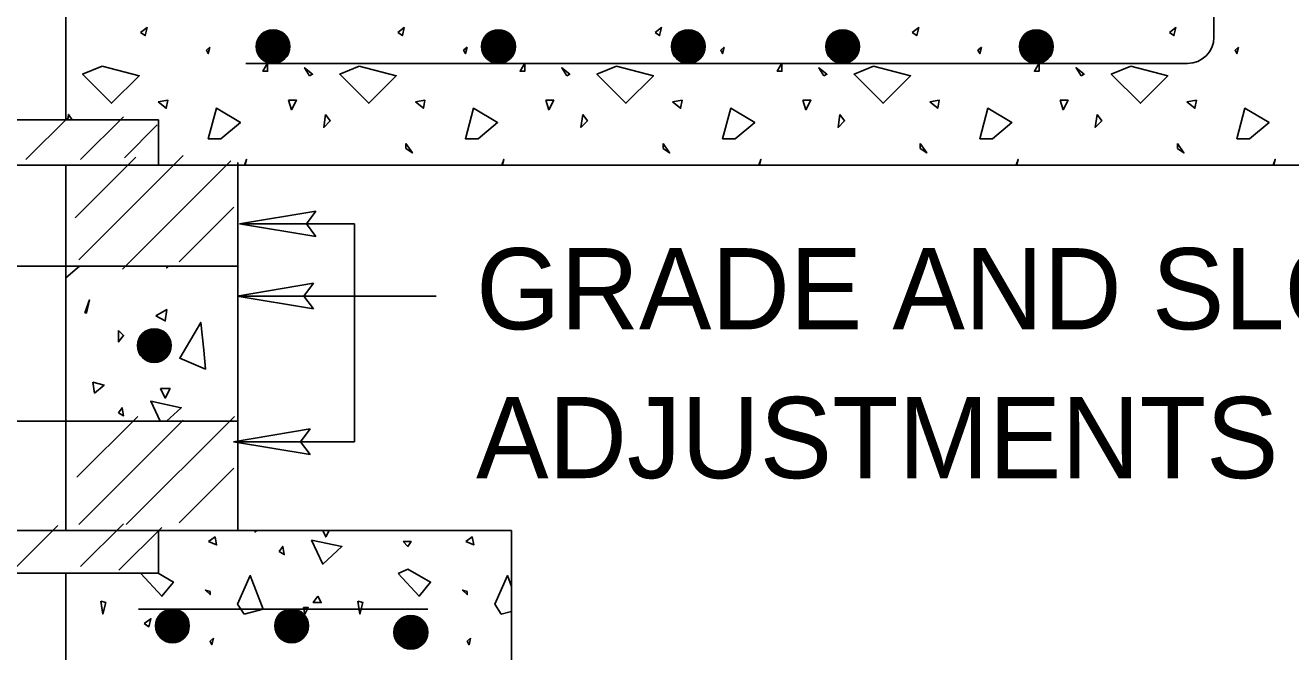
# Model space of a CAD drawing. Extents: x 5.8 to 18, y -5.2 to 5.4.
# Drawn here: x 7.706 to 8.641, y -0.7 to -0.237 of the extents above; entities that cross this region are included whole.
import ezdxf

# ---------------------------------------------------------------- set-up
doc = ezdxf.new("R2010")
doc.units = 0
for name, color, linetype in [('DETL-DIMS', 7, 'Continuous'), ('DETL-LINE', 7, 'Continuous'), ('DETL-NOTE', 7, 'Continuous'), ('DETL-PATT', 7, 'Continuous')]:
    doc.layers.add(name, color=color, linetype=linetype)

msp = doc.modelspace()

# ---------------------------------------------------------------- linework, layer by layer
at = {"layer": 'DETL-DIMS'}
for p, q in [((7.92051, -0.37424), (7.86404, -0.38365)), ((7.92051, -0.37424), (7.91345, -0.38365)), ((7.9491, -0.38365), (7.86404, -0.38365)), ((7.92051, -0.39306), (7.86404, -0.38365)), ((7.92051, -0.39306), (7.91345, -0.38365)), ((7.9491, -0.43695), (7.9491, -0.38365)), ((7.91871, -0.42753), (7.86224, -0.43695)), ((7.91871, -0.42753), (7.91165, -0.43695)), ((7.9491, -0.43695), (7.86224, -0.43695)), ((7.91871, -0.44636), (7.86224, -0.43695)), ((7.91871, -0.44636), (7.91165, -0.43695)), ((8.00945, -0.43695), (7.9491, -0.43695)), ((7.9491, -0.43695), (7.9491, -0.54459)), ((7.91612, -0.53518), (7.85965, -0.54459)), ((7.91612, -0.53518), (7.90906, -0.54459)), ((7.9491, -0.54459), (7.85965, -0.54459)), ((7.91612, -0.554), (7.85965, -0.54459)), ((7.91612, -0.554), (7.90906, -0.54459))]:
    msp.add_line(p, q, dxfattribs=at)
at = {"layer": 'DETL-LINE'}
for p, q in [((8.58404, -0.24561), (8.58404, -0.00424)), ((7.73561, -0.15436), (7.73561, -0.30671)), ((8.56443, -0.2651), (7.86878, -0.2651)), ((7.09643, -0.30671), (7.80416, -0.30671)), ((7.80416, -0.30671), (7.80416, -0.34028)), ((7.03698, -0.34028), (8.65804, -0.34028)), ((7.73561, -0.34028), (7.73561, -0.61012)), ((7.86275, -0.33832), (7.86275, -0.61012)), ((7.86275, -0.41498), (7.03698, -0.41498)), ((7.86275, -0.52942), (7.03698, -0.52942)), ((6.87914, -0.61012), (8.0651, -0.61012)), ((7.80416, -0.61012), (7.80416, -0.64173)), ((8.0651, -2.13177), (8.0651, -0.61012)), ((7.09643, -0.64173), (7.80416, -0.64173)), ((7.73561, -0.64173), (7.73561, -0.73934)), ((7.78929, -0.6682), (8.00329, -0.6682))]:
    msp.add_line(p, q, dxfattribs=at)
for centre, radius in [((7.88878, -0.25264), 0.01247), ((7.88868, -0.25253), 0.01163), ((7.88756, -0.25253), 0.01009), ((7.88881, -0.25283), 0.01122), ((7.88915, -0.25336), 0.011), ((7.88909, -0.25296), 0.01024), ((8.05537, -0.25264), 0.01247), ((8.05527, -0.25253), 0.01163), ((8.05415, -0.25253), 0.01009), ((8.0554, -0.25283), 0.01122), ((8.05574, -0.25336), 0.011), ((8.05568, -0.25296), 0.01024), ((8.19565, -0.25264), 0.01247), ((8.19554, -0.25253), 0.01163), ((8.19442, -0.25253), 0.01009), ((8.19568, -0.25283), 0.01122), ((8.19601, -0.25336), 0.011), ((8.19595, -0.25296), 0.01024), ((8.30965, -0.25264), 0.01247), ((8.30954, -0.25253), 0.01163), ((8.30842, -0.25253), 0.01009), ((8.30968, -0.25283), 0.01122), ((8.31001, -0.25336), 0.011), ((8.30995, -0.25296), 0.01024), ((8.45282, -0.25264), 0.01247), ((8.45272, -0.25253), 0.01163), ((8.4516, -0.25253), 0.01009), ((8.45285, -0.25283), 0.01122), ((8.45319, -0.25336), 0.011), ((8.45313, -0.25296), 0.01024), ((7.88797, -0.25204), 0.00834), ((7.88936, -0.25302), 0.00969), ((7.88944, -0.2533), 0.00918), ((7.88778, -0.25302), 0.00724), ((7.88958, -0.25343), 0.00876), ((7.88944, -0.25365), 0.00835), ((7.88715, -0.25343), 0.00578), ((7.88966, -0.25365), 0.00814), ((7.8895, -0.25351), 0.00786), ((7.88985, -0.25371), 0.00751), ((7.88993, -0.25357), 0.00704), ((7.88999, -0.25349), 0.00655), ((7.88811, -0.25316), 0.00467), ((7.88999, -0.25336), 0.006), ((7.89007, -0.25351), 0.00565), ((7.89007, -0.25357), 0.0051), ((7.89029, -0.254), 0.00488), ((7.8904, -0.25406), 0.00445), ((7.8904, -0.25394), 0.0039), ((7.89056, -0.25385), 0.00377), ((7.89056, -0.2542), 0.00347), ((7.8907, -0.25392), 0.00333), ((7.89076, -0.254), 0.00285), ((7.89056, -0.25379), 0.00238), ((7.89083, -0.25408), 0.00212), ((7.89091, -0.25406), 0.00175), ((8.05456, -0.25204), 0.00834), ((8.05595, -0.25302), 0.00969), ((8.05603, -0.2533), 0.00918), ((8.05436, -0.25302), 0.00724), ((8.05617, -0.25343), 0.00876), ((8.05603, -0.25365), 0.00835), ((8.05374, -0.25343), 0.00578), ((8.05625, -0.25365), 0.00814), ((8.05609, -0.25351), 0.00786), ((8.05644, -0.25371), 0.00751), ((8.05652, -0.25357), 0.00704), ((8.05658, -0.25349), 0.00655), ((8.0547, -0.25316), 0.00467), ((8.05658, -0.25336), 0.006), ((8.05666, -0.25351), 0.00565), ((8.05666, -0.25357), 0.0051), ((8.05687, -0.254), 0.00488), ((8.05699, -0.25406), 0.00445), ((8.05699, -0.25394), 0.0039), ((8.05715, -0.25385), 0.00377), ((8.05715, -0.2542), 0.00347), ((8.05729, -0.25392), 0.00333), ((8.05734, -0.254), 0.00285), ((8.05715, -0.25379), 0.00238), ((8.05742, -0.25408), 0.00212), ((8.0575, -0.25406), 0.00175), ((8.19483, -0.25204), 0.00834), ((8.19623, -0.25302), 0.00969), ((8.19631, -0.2533), 0.00918), ((8.19464, -0.25302), 0.00724), ((8.19644, -0.25343), 0.00876), ((8.19631, -0.25365), 0.00835), ((8.19401, -0.25343), 0.00578), ((8.19652, -0.25365), 0.00814), ((8.19636, -0.25351), 0.00786), ((8.19672, -0.25371), 0.00751), ((8.1968, -0.25357), 0.00704), ((8.19497, -0.25316), 0.00467), ((8.19685, -0.25349), 0.00655), ((8.19685, -0.25336), 0.006), ((8.19693, -0.25351), 0.00565), ((8.19693, -0.25357), 0.0051), ((8.19715, -0.254), 0.00488), ((8.19727, -0.25406), 0.00445), ((8.19727, -0.25394), 0.0039), ((8.19742, -0.25385), 0.00377), ((8.19742, -0.2542), 0.00347), ((8.19756, -0.25392), 0.00333), ((8.19762, -0.254), 0.00285), ((8.19742, -0.25379), 0.00238), ((8.1977, -0.25408), 0.00212), ((8.19778, -0.25406), 0.00175), ((8.30883, -0.25204), 0.00834), ((8.31023, -0.25302), 0.00969), ((8.31031, -0.2533), 0.00918), ((8.30864, -0.25302), 0.00724), ((8.31044, -0.25343), 0.00876), ((8.31031, -0.25365), 0.00835), ((8.30801, -0.25343), 0.00578), ((8.31052, -0.25365), 0.00814), ((8.31036, -0.25351), 0.00786), ((8.31072, -0.25371), 0.00751), ((8.3108, -0.25357), 0.00704), ((8.30897, -0.25316), 0.00467), ((8.31085, -0.25349), 0.00655), ((8.31085, -0.25336), 0.006), ((8.31093, -0.25351), 0.00565), ((8.31093, -0.25357), 0.0051), ((8.31115, -0.254), 0.00488), ((8.31127, -0.25406), 0.00445), ((8.31127, -0.25394), 0.0039), ((8.31142, -0.25385), 0.00377), ((8.31142, -0.2542), 0.00347), ((8.31156, -0.25392), 0.00333), ((8.31162, -0.254), 0.00285), ((8.31142, -0.25379), 0.00238), ((8.3117, -0.25408), 0.00212), ((8.31178, -0.25406), 0.00175), ((8.45201, -0.25204), 0.00834), ((8.4534, -0.25302), 0.00969), ((8.45348, -0.2533), 0.00918), ((8.45181, -0.25302), 0.00724), ((8.45362, -0.25343), 0.00876), ((8.45348, -0.25365), 0.00835), ((8.45119, -0.25343), 0.00578), ((8.4537, -0.25365), 0.00814), ((8.45354, -0.25351), 0.00786), ((8.45389, -0.25371), 0.00751), ((8.45397, -0.25357), 0.00704), ((8.45403, -0.25349), 0.00655), ((8.45215, -0.25316), 0.00467), ((8.45403, -0.25336), 0.006), ((8.45411, -0.25351), 0.00565), ((8.45411, -0.25357), 0.0051), ((8.45432, -0.254), 0.00488), ((8.45444, -0.25406), 0.00445), ((8.45444, -0.25394), 0.0039), ((8.4546, -0.25385), 0.00377), ((8.4546, -0.2542), 0.00347), ((8.45474, -0.25392), 0.00333), ((8.4548, -0.254), 0.00285), ((8.4546, -0.25379), 0.00238), ((8.45487, -0.25408), 0.00212), ((8.45495, -0.25406), 0.00175), ((7.89105, -0.25414), 0.00133), ((7.89105, -0.254), 0.00118), ((7.89146, -0.25406), 0.00148), ((7.89103, -0.254), 0.000769), ((7.89089, -0.254), 0.000362), ((7.89119, -0.254), 0.00023), ((8.05764, -0.25414), 0.00133), ((8.05764, -0.254), 0.00118), ((8.05805, -0.25406), 0.00148), ((8.05762, -0.254), 0.000769), ((8.05748, -0.254), 0.000362), ((8.05778, -0.254), 0.00023), ((8.19791, -0.25414), 0.00133), ((8.19791, -0.254), 0.00118), ((8.19832, -0.25406), 0.00148), ((8.19789, -0.254), 0.000769), ((8.19776, -0.254), 0.000362), ((8.19805, -0.254), 0.00023), ((8.31191, -0.25414), 0.00133), ((8.31191, -0.254), 0.00118), ((8.31232, -0.25406), 0.00148), ((8.31189, -0.254), 0.000769), ((8.31176, -0.254), 0.000362), ((8.31205, -0.254), 0.00023), ((8.45509, -0.25414), 0.00133), ((8.45509, -0.254), 0.00118), ((8.4555, -0.25406), 0.00148), ((8.45507, -0.254), 0.000769), ((8.45493, -0.254), 0.000362), ((8.45523, -0.254), 0.00023), ((7.80106, -0.47357), 0.01247), ((7.80095, -0.47346), 0.01163), ((7.79983, -0.47346), 0.01009), ((7.80109, -0.47376), 0.01122), ((7.80142, -0.47429), 0.011), ((7.80136, -0.4739), 0.01024), ((7.80025, -0.47297), 0.00834), ((7.80164, -0.47395), 0.00969), ((7.80172, -0.47423), 0.00918), ((7.80005, -0.47395), 0.00724), ((7.80185, -0.47437), 0.00876), ((7.80172, -0.47458), 0.00835), ((7.80193, -0.47458), 0.00814), ((7.80178, -0.47444), 0.00786), ((7.80213, -0.47464), 0.00751), ((7.80221, -0.4745), 0.00704), ((7.79942, -0.47437), 0.00578), ((7.80038, -0.47409), 0.00467), ((7.80227, -0.47442), 0.00655), ((7.80227, -0.47429), 0.006), ((7.80234, -0.47444), 0.00565), ((7.80234, -0.4745), 0.0051), ((7.80256, -0.47493), 0.00488), ((7.80268, -0.47499), 0.00445), ((7.80268, -0.47488), 0.0039), ((7.80283, -0.47478), 0.00377), ((7.80283, -0.47513), 0.00347), ((7.80297, -0.47486), 0.00333), ((7.80303, -0.47493), 0.00285), ((7.80283, -0.47472), 0.00238), ((7.80311, -0.47501), 0.00212), ((7.80319, -0.47499), 0.00175), ((7.80332, -0.47507), 0.00133), ((7.80332, -0.47493), 0.00118), ((7.80374, -0.47499), 0.00148), ((7.80331, -0.47493), 0.000769), ((7.80317, -0.47493), 0.000362), ((7.80346, -0.47493), 0.00023), ((7.81447, -0.68067), 0.01247), ((7.81436, -0.68056), 0.01163), ((7.81325, -0.68056), 0.01009), ((7.8145, -0.68086), 0.01122), ((7.81483, -0.68139), 0.011), ((7.81478, -0.68099), 0.01024), ((7.81366, -0.68007), 0.00834), ((7.81505, -0.68105), 0.00969), ((7.81513, -0.68133), 0.00918), ((7.81527, -0.68146), 0.00876), ((7.90251, -0.68067), 0.01247), ((7.9024, -0.68056), 0.01163), ((7.90129, -0.68056), 0.01009), ((7.90254, -0.68086), 0.01122), ((7.90287, -0.68139), 0.011), ((7.90281, -0.68099), 0.01024), ((7.9017, -0.68007), 0.00834), ((7.90309, -0.68105), 0.00969), ((7.90317, -0.68133), 0.00918), ((7.90331, -0.68146), 0.00876), ((7.9906, -0.68538), 0.01247), ((7.81346, -0.68105), 0.00724), ((7.81513, -0.68168), 0.00835), ((7.81283, -0.68146), 0.00578), ((7.81534, -0.68168), 0.00814), ((7.81519, -0.68154), 0.00786), ((7.81554, -0.68174), 0.00751), ((7.81562, -0.6816), 0.00704), ((7.8138, -0.68119), 0.00467), ((7.81568, -0.68152), 0.00655), ((7.81568, -0.68139), 0.006), ((7.81576, -0.68154), 0.00565), ((7.81576, -0.6816), 0.0051), ((7.81597, -0.68203), 0.00488), ((7.81609, -0.68209), 0.00445), ((7.81609, -0.68197), 0.0039), ((7.81625, -0.68188), 0.00377), ((7.81625, -0.68223), 0.00347), ((7.81638, -0.68195), 0.00333), ((7.81644, -0.68203), 0.00285), ((7.81625, -0.68182), 0.00238), ((7.81652, -0.68211), 0.00212), ((7.8166, -0.68209), 0.00175), ((7.81674, -0.68217), 0.00133), ((7.81674, -0.68203), 0.00118), ((7.81715, -0.68209), 0.00148), ((7.81672, -0.68203), 0.000769), ((7.81658, -0.68203), 0.000362), ((7.81687, -0.68203), 0.00023), ((7.9015, -0.68105), 0.00724), ((7.90317, -0.68168), 0.00835), ((7.90087, -0.68146), 0.00578), ((7.90338, -0.68168), 0.00814), ((7.90323, -0.68154), 0.00786), ((7.90358, -0.68174), 0.00751), ((7.90366, -0.6816), 0.00704), ((7.90183, -0.68119), 0.00467), ((7.90372, -0.68152), 0.00655), ((7.90372, -0.68139), 0.006), ((7.9038, -0.68154), 0.00565), ((7.9038, -0.6816), 0.0051), ((7.90401, -0.68203), 0.00488), ((7.90413, -0.68209), 0.00445), ((7.90413, -0.68197), 0.0039), ((7.90429, -0.68188), 0.00377), ((7.90429, -0.68223), 0.00347), ((7.90442, -0.68195), 0.00333), ((7.90448, -0.68203), 0.00285), ((7.90429, -0.68182), 0.00238), ((7.90456, -0.68211), 0.00212), ((7.90464, -0.68209), 0.00175), ((7.90478, -0.68217), 0.00133), ((7.90478, -0.68203), 0.00118), ((7.90519, -0.68209), 0.00148), ((7.90476, -0.68203), 0.000769), ((7.90462, -0.68203), 0.000362), ((7.90491, -0.68203), 0.00023), ((7.99049, -0.68528), 0.01163), ((7.98937, -0.68528), 0.01009), ((7.99063, -0.68557), 0.01122), ((7.99096, -0.6861), 0.011), ((7.9909, -0.68571), 0.01024), ((7.98978, -0.68479), 0.00834), ((7.99118, -0.68577), 0.00969), ((7.99125, -0.68604), 0.00918), ((7.98959, -0.68577), 0.00724), ((7.99139, -0.68618), 0.00876), ((7.99125, -0.6864), 0.00835), ((7.98896, -0.68618), 0.00578), ((7.99147, -0.6864), 0.00814), ((7.99131, -0.68626), 0.00786), ((7.99167, -0.68646), 0.00751), ((7.99175, -0.68632), 0.00704), ((7.9918, -0.68624), 0.00655), ((7.98992, -0.68591), 0.00467), ((7.9918, -0.6861), 0.006), ((7.99188, -0.68626), 0.00565), ((7.99188, -0.68632), 0.0051), ((7.9921, -0.68675), 0.00488), ((7.99222, -0.68681), 0.00445), ((7.99222, -0.68669), 0.0039), ((7.99237, -0.68659), 0.00377), ((7.99237, -0.68695), 0.00347), ((7.99251, -0.68667), 0.00333), ((7.99257, -0.68675), 0.00285), ((7.99237, -0.68653), 0.00238), ((7.99265, -0.68683), 0.00212), ((7.99273, -0.68681), 0.00175), ((7.99286, -0.68689), 0.00133), ((7.99286, -0.68675), 0.00118), ((7.99327, -0.68681), 0.00148), ((7.99284, -0.68675), 0.000769), ((7.99271, -0.68675), 0.000362), ((7.993, -0.68675), 0.00023)]:
    msp.add_circle(centre, radius, dxfattribs=at)
msp.add_arc((8.56444, -0.24549), 0.01961, 270, 359.62102, dxfattribs=at)
at = {"layer": 'DETL-PATT'}
for p, q in [((7.70616, -0.33616), (7.7378, -0.30451)), ((7.74663, -0.33616), (7.77827, -0.30451)), ((7.77898, -0.33479), (7.80325, -0.31051)), ((7.74255, -0.37926), (7.78741, -0.3344)), ((7.74525, -0.41032), (7.82251, -0.33306)), ((7.77765, -0.41702), (7.85757, -0.3371)), ((7.81941, -0.41161), (7.85973, -0.3713)), ((7.74392, -0.57071), (7.78878, -0.52585)), ((7.74525, -0.60585), (7.82251, -0.52859)), ((7.78031, -0.60581), (7.86024, -0.52589)), ((7.81941, -0.60444), (7.85973, -0.56412)), ((7.69808, -0.6382), (7.72973, -0.60655)), ((7.74663, -0.63683), (7.77827, -0.60518)), ((7.77494, -0.63953), (7.80659, -0.60789))]:
    msp.add_line(p, q, dxfattribs=at)
for points in [[(7.79098, -0.24228), (7.79439, -0.24455), (7.7958, -0.23863)], [(7.98102, -0.24228), (7.98439, -0.24455), (7.9858, -0.23863)], [(8.17106, -0.24228), (8.17443, -0.24455), (8.17584, -0.23863)], [(8.36106, -0.24228), (8.36447, -0.24455), (8.36588, -0.23863)], [(8.5511, -0.24228), (8.55447, -0.24455), (8.55588, -0.23863)], [(7.84212, -0.25302), (7.83957, -0.2553), (7.84098, -0.25781)], [(8.03212, -0.25302), (8.02957, -0.2553), (8.03098, -0.25781)], [(8.22216, -0.25302), (8.21961, -0.2553), (8.22102, -0.25781)], [(8.41216, -0.25302), (8.40965, -0.2553), (8.41106, -0.25781)], [(8.6022, -0.25302), (8.59965, -0.2553), (8.60106, -0.25781)], [(7.76247, -0.26714), (7.78988, -0.2742), (7.76953, -0.29451), (7.74808, -0.27306)], [(7.88475, -0.26487), (7.88133, -0.27083), (7.88475, -0.27083)], [(7.9158, -0.2742), (7.91804, -0.27306), (7.91212, -0.26828)], [(7.95251, -0.26714), (7.97988, -0.2742), (7.95957, -0.29451), (7.93812, -0.27306)], [(8.07475, -0.26487), (8.07137, -0.27083), (8.07475, -0.27083)], [(8.1058, -0.2742), (8.10808, -0.27306), (8.10216, -0.26828)], [(8.14251, -0.26714), (8.16992, -0.2742), (8.14957, -0.29451), (8.12812, -0.27306)], [(8.26478, -0.26487), (8.26141, -0.27083), (8.26478, -0.27083)], [(8.29584, -0.2742), (8.29812, -0.27306), (8.29216, -0.26828)], [(8.33255, -0.26714), (8.35992, -0.2742), (8.33961, -0.29451), (8.31816, -0.27306)], [(8.45482, -0.26487), (8.45141, -0.27083), (8.45482, -0.27083)], [(8.48588, -0.2742), (8.48812, -0.27306), (8.4822, -0.26828)], [(8.52259, -0.26714), (8.54996, -0.2742), (8.52965, -0.29451), (8.50816, -0.27306)], [(7.804, -0.29342), (7.80992, -0.2982), (7.81106, -0.29228)], [(7.85027, -0.32079), (7.86471, -0.30863), (7.8469, -0.2982), (7.84098, -0.32079)], [(7.90027, -0.29228), (7.90251, -0.29934), (7.9062, -0.29228)], [(7.994, -0.29342), (7.99992, -0.2982), (8.00106, -0.29228)], [(8.04031, -0.32079), (8.05471, -0.30863), (8.03694, -0.2982), (8.03098, -0.32079)], [(8.09027, -0.29228), (8.09255, -0.29934), (8.09624, -0.29228)], [(8.18404, -0.29342), (8.18996, -0.2982), (8.1911, -0.29228)], [(8.23035, -0.32079), (8.24475, -0.30863), (8.22694, -0.2982), (8.22102, -0.32079)], [(8.28031, -0.29228), (8.28259, -0.29934), (8.28624, -0.29228)], [(8.37404, -0.29342), (8.38, -0.2982), (8.3811, -0.29228)], [(8.42035, -0.32079), (8.43475, -0.30863), (8.41698, -0.2982), (8.41106, -0.32079)], [(8.47035, -0.29228), (8.47259, -0.29934), (8.47627, -0.29228)], [(8.56408, -0.29342), (8.57, -0.2982), (8.57114, -0.29228)], [(8.61039, -0.32079), (8.62478, -0.30863), (8.60698, -0.2982), (8.60106, -0.32079)], [(7.92765, -0.30271), (7.92624, -0.31232), (7.93106, -0.30753)], [(8.11769, -0.30271), (8.11627, -0.31232), (8.12106, -0.30753)], [(8.30769, -0.30271), (8.30627, -0.31232), (8.3111, -0.30753)], [(8.49773, -0.30271), (8.49631, -0.31232), (8.5011, -0.30753)], [(7.98694, -0.32416), (7.98694, -0.32785), (7.99176, -0.33122)], [(8.17698, -0.32416), (8.17698, -0.32785), (8.18176, -0.33122)], [(8.36698, -0.32416), (8.36698, -0.32785), (8.3718, -0.33122)], [(8.55702, -0.32416), (8.55702, -0.32785), (8.5618, -0.33122)], [(7.74984, -0.44942), (7.75098, -0.44942), (7.75322, -0.43985)], [(7.80208, -0.45169), (7.80914, -0.45538), (7.81027, -0.44691)], [(7.83765, -0.47683), (7.83878, -0.49095), (7.81984, -0.48275), (7.83537, -0.45648)], [(7.77467, -0.46244), (7.77467, -0.47091), (7.77835, -0.46608)], [(7.75576, -0.50055), (7.7569, -0.50871), (7.76396, -0.50279)], [(7.80573, -0.50534), (7.80914, -0.5124), (7.81278, -0.50534)], [(7.77467, -0.52314), (7.77835, -0.52538), (7.77722, -0.51946)], [(7.84114, -0.61832), (7.84706, -0.62087), (7.84592, -0.61495)], [(8.03118, -0.61832), (8.0371, -0.62087), (8.03596, -0.61495)], [(7.89337, -0.62569), (7.89706, -0.62793), (7.89592, -0.622)], [(7.9171, -0.61722), (7.92557, -0.63498), (7.93969, -0.622)], [(7.98486, -0.61832), (7.98851, -0.622), (7.99078, -0.61832)], [(7.86741, -0.67197), (7.88153, -0.66832), (7.87192, -0.64346), (7.86259, -0.66463)], [(7.98118, -0.64204), (7.99671, -0.65871), (8.00518, -0.64828), (7.98851, -0.63867)], [(7.84227, -0.65534), (7.83886, -0.6542), (7.84227, -0.65757)], [(8.03227, -0.65534), (8.0289, -0.6542), (8.03227, -0.65757)], [(7.76153, -0.6624), (7.76294, -0.67197), (7.76518, -0.66349)], [(7.92188, -0.65871), (7.92443, -0.66349), (7.91851, -0.66349)], [(7.95153, -0.6624), (7.95294, -0.67197), (7.95522, -0.66349)], [(7.91118, -0.66718), (7.91227, -0.67197), (7.91482, -0.66718)], [(7.79369, -0.67902), (7.7971, -0.6813), (7.79851, -0.67538)], [(7.98373, -0.67902), (7.9871, -0.6813), (7.98851, -0.67538)], [(7.84482, -0.68977), (7.84227, -0.69204), (7.84369, -0.69455)], [(8.03482, -0.68977), (8.03227, -0.69204), (8.03369, -0.69455)]]:
    msp.add_lwpolyline(points, close=True, dxfattribs=at)
for points in [[(7.74047, -0.30671), (7.73765, -0.30271), (7.73706, -0.30671)], [(7.8682, -0.34028), (7.86922, -0.33604), (7.86773, -0.34028)], [(8.05824, -0.34028), (8.05922, -0.33604), (8.05773, -0.34028)], [(8.24827, -0.34028), (8.24925, -0.33604), (8.24776, -0.34028)], [(8.43827, -0.34028), (8.43929, -0.33604), (8.4378, -0.34028)], [(8.62831, -0.34028), (8.62929, -0.33604), (8.6278, -0.34028)], [(7.73561, -0.42349), (7.74569, -0.41498)], [(7.81043, -0.41498), (7.81027, -0.41612), (7.81137, -0.41498)], [(7.81016, -0.52942), (7.82098, -0.51946), (7.79839, -0.51467), (7.80541, -0.52942)], [(7.87541, -0.61012), (7.87557, -0.61126), (7.87694, -0.61012)], [(7.92553, -0.61012), (7.9278, -0.61495), (7.93031, -0.61012)], [(7.79184, -0.64173), (7.79118, -0.64204), (7.80671, -0.65871), (7.81518, -0.64828), (7.80384, -0.64173)], [(8.0651, -0.65165), (8.06192, -0.64346), (8.05263, -0.66463), (8.05741, -0.67197), (8.0651, -0.67)]]:
    msp.add_lwpolyline(points, dxfattribs=at)

# ---------------------------------------------------------------- texts
at = {"layer": 'DETL-NOTE'}
for s, p in [('GRADE AND SLOPE', (8.03886, -0.46153)), ('ADJUSTMENTS SEE NOTE 6', (8.03886, -0.57153))]:
    msp.add_text(s, height=0.06, dxfattribs=at).set_placement(p)

doc.saveas('drawing.dxf')
